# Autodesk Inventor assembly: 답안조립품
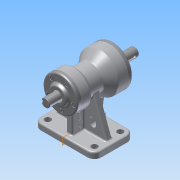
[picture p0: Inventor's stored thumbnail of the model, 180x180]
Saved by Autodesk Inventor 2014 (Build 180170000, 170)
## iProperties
Created: 2015-08
Part Number: 답안조립품
Document SubType Name: Assembly
Designer: study
Author: study
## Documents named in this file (10)
- C:\Users\study\Desktop\450805V1026\답안조립품.iam
- C:\Users\study\Desktop\450805V1026\1-본체.ipt
- C:\Users\study\Desktop\450805V1026\베어링 6203.ipt
- C:\Users\study\Desktop\450805V1026\M4x0.5.ipt
- C:\Users\study\Desktop\450805V1026\뒤커버.ipt
- C:\Users\study\Desktop\450805V1026\축.ipt
- C:\Users\study\Desktop\450805V1026\베어링 6205.ipt
- C:\Users\study\Desktop\450805V1026\앞커버.ipt
- C:\Users\study\Desktop\450805V1026\오일실 .ipt
- 오일실 .ipt
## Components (11 placed, 2 different names)
1. 1-본체:1
2. M4x0.5:1
3. M4x0.5:2
4. M4x0.5:3
5. M4x0.5:4
6. M4x0.5:5
7. M4x0.5:6
8. M4x0.5:7
9. M4x0.5:8
10. M4x0.5:9
11. M4x0.5:10
